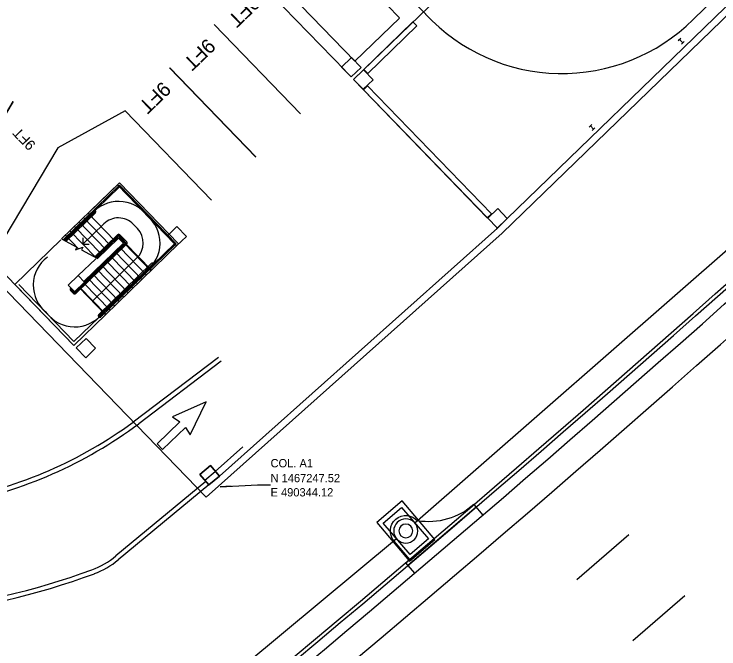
# Model space of a CAD drawing. Extents: x 468143 to 491361, y 1438528 to 1468730.
# Drawn here: x 490314.2 to 490416.5, y 1467224 to 1467316.1 of the extents above; entities that cross this region are included whole.
import ezdxf

# ---------------------------------------------------------------- set-up
doc = ezdxf.new("R2010")
doc.units = 0
doc.layers.add('Default', color=7, linetype='Continuous')
doc.layers.add('Xreference_dp', color=7, linetype='Continuous')

# ---------------------------------------------------------------- blocks, each defined once
blk = doc.blocks.new('POINT_DISPLAY')
at = {"layer": 'Default'}
blk.add_line((0, 0), (0, 0), dxfattribs=at)
blk = doc.blocks.new('InltCurb1_35')
at = {"layer": 'Default'}
for p, q in [((2.25, 2), (2.25, 5.5)), ((-10, 2), (-10, 0)), ((-10, 1.5), (3, 1.5)), ((3, 2), (2.25, 2)), ((3, 0), (3, 2))]:
    blk.add_line(p, q, dxfattribs=at)
for radius in [1.75, 1]:
    blk.add_circle((0, 5.5), radius, dxfattribs=at)
for centre, radius, start, end in [((0, 5.5), 2.25, 0, 180), ((-9.85, 12), 10, 269.1432, 319.4677)]:
    blk.add_arc(centre, radius, start, end, dxfattribs=at)
for p in [(0, 7.75), (0, 7.25), (0, 7.25), (-1.6, 6.2), (-1.22, 6.76), (-0.66, 7.12), (0.7, 7.1), (1.26, 6.72), (1.62, 6.16), (-1.75, 5.5), (-1.75, 5.5), (0, 5.5), (0, 5.5), (1.75, 5.5), (1.75, 5.5), (-1.62, 4.84), (-1.26, 4.28), (1.22, 4.24), (1.6, 4.8), (-0.7, 3.9), (0, 3.75), (0, 3.75), (0.66, 3.88), (0, 0), (0, 0)]:
    blk.add_blockref('POINT_DISPLAY', p, dxfattribs=at)
blk = doc.blocks.new('JBottom35x60')
at = {"layer": 'Default'}
for p, q in [((2.42, 3.67), (-2.42, 3.67)), ((-2.42, 3.67), (-2.42, -3.67)), ((2.42, -3.67), (2.42, 3.67)), ((-1.75, -3), (-1.75, 3)), ((-1.75, 3), (1.75, 3)), ((1.75, 3), (1.75, -3)), ((1.75, -3), (-1.75, -3)), ((-2.42, -3.67), (2.42, -3.67))]:
    blk.add_line(p, q, dxfattribs=at)
for p in [(-1.75, 3), (0, 3), (0, 3), (0, 3), (1.75, 3), (-1.75, 0), (-1.75, 0), (0, 0), (0, 0), (0, 0), (1.75, 0), (1.75, 0), (-1.75, -3), (0, -3), (0, -3), (0, -3), (1.75, -3)]:
    blk.add_blockref('POINT_DISPLAY', p, dxfattribs=at)
blk = doc.blocks.new('STALL 9FT')
at = {"layer": 'Default'}
for points in [[(0, 0), (0, 216)], [(108, 216), (108, 0)]]:
    blk.add_lwpolyline(points, dxfattribs=at)
blk.add_text('9FT', height=25, dxfattribs=at).set_placement((24.7, 7.1))
blk = doc.blocks.new('arrow-thru')
at = {"layer": 'Default'}
blk.add_lwpolyline([(14.99997, 0), (28.999942, 0), (28.999942, 54.99989), (43.999912, 51.999896), (21.999956, 111.999776), (0, 51.999896), (14.99997, 54.99989)], close=True, dxfattribs=at)
blk = doc.blocks.new('Col 16x24')
at = {"layer": 'Default'}
blk.add_lwpolyline([(11.999976, -7.999984), (-11.999976, -7.999984), (-11.999976, 7.999984), (11.999976, 7.999984), (11.999976, -7.999984)], dxfattribs=at)
blk.add_lwpolyline([(-11.999976, -7.999984), (11.999976, -7.999984), (11.999976, 7.999984), (-11.999976, 7.999984)], close=True, dxfattribs=at)
blk = doc.blocks.new('staire lvl 1')
at = {"layer": 'Default'}
for p, q in [((158.5, 259.5), (10.5, 259.5)), ((10.5, 182.5), (10.5, 259.5)), ((158.5, 147.9), (158.5, 259.5)), ((15.5, 254.5), (153.5, 254.5)), ((15.5, 193.5), (15.5, 254.5)), ((76, 197), (83, 197)), ((13.5, 191.5), (13.5, 8.5)), ((15.5, 191.5), (15.5, 10.5)), ((17, 191.5), (17, 63.5)), ((19, 191.5), (19, 63.5)), ((73, 194), (73, 71)), ((75, 194), (75, 71)), ((76, 195), (83, 195)), ((10.5, 182.5), (76.5, 182.5)), ((10.5, 182.5), (10.5, 5.5)), ((10.5, 181.5), (76.5, 181.5)), ((43.5, 182.5), (43.5, 74.5)), ((10.5, 171.5), (76.5, 171.5)), ((10.5, 160.5), (76.5, 160.5)), ((76.5, 71.5), (76.5, 169.5)), ((76.5, 169.5), (76.5, 71.5)), ((78.5, 169.5), (78.5, 73.5)), ((92.5, 169.5), (92.5, 127.1)), ((92.5, 127.1), (92.5, 169.5)), ((10.5, 149.5), (76.5, 149.5)), ((10.5, 138.5), (76.5, 138.5)), ((158.5, 136.5), (125.7, 136.5)), ((150, 143.6), (150, 72.2)), ((152, 144.1), (152, 72.2)), ((153.5, 144.5), (153.5, 10.5)), ((153.5, 144.5), (153.5, 72.2)), ((155.5, 145.1), (155.5, 8.5)), ((155.5, 145.1), (155.5, 72.2)), ((158.5, 5.5), (158.5, 145.9)), ((10.5, 127.5), (76.5, 127.5)), ((90.5, 124.6), (90.5, 73.5)), ((92.5, 71.5), (92.5, 125.1)), ((92.5, 125.1), (92.5, 71.5)), ((158.5, 125.5), (93.9, 125.5)), ((94, 125.5), (94, 71)), ((96, 126.1), (96, 71)), ((126.2, 125.5), (126.2, 74.5)), ((10.5, 116.5), (76.5, 116.5)), ((158.5, 114.5), (92.5, 114.5)), ((10.5, 105.5), (76.5, 105.5)), ((158.5, 103.5), (92.5, 103.5)), ((10.5, 94.5), (76.5, 94.5)), ((158.5, 92.5), (92.5, 92.5)), ((10.5, 83.5), (76.5, 83.5)), ((15.5, 83.5), (15.5, 10.5)), ((158.5, 81.5), (92.5, 81.5)), ((158.5, 10.5), (158.5, 81.5)), ((76.5, 72.5), (10.5, 72.5)), ((10.5, 71.5), (76.5, 71.5)), ((15.5, 62), (16, 62)), ((76, 70), (93, 70)), ((76, 68), (93, 68)), ((76.5, 71.5), (92.5, 71.5)), ((76.5, 71.5), (92.5, 71.5)), ((78.5, 73.5), (90.5, 73.5)), ((152.7, 71.5), (153.5, 71.5)), ((152.7, 69.5), (153.5, 69.5)), ((15.5, 60), (16, 60)), ((90.2, 38.5), (79.5, 38.5)), ((10.5, 10.5), (158.5, 10.5)), ((158.5, 5.5), (10.5, 5.5)), ((155.5, 8.5), (13.5, 8.5)), ((153.5, 10.5), (15.5, 10.5))]:
    blk.add_line(p, q, dxfattribs=at)
for points in [[(158.5, 145.9), (129.6, 136.7), (128.3, 141.7), (122.2, 129.3), (120.9, 134.3), (90.5, 124.6)], [(133.9, 117.9), (126.2, 125.5), (118.6, 117.9)]]:
    blk.add_lwpolyline(points, dxfattribs=at)
for centre, radius, start, end in [((76.5, 193.5), 61, 82.5761, 187.4239), ((92.5, 193.5), 61, 352.5776, 97.4223), ((76, 194), 3, 90, 180), ((83, 194), 3, 360, 90), ((16.2, 191.5), 2.75, 360, 180), ((14.5, 186.5), 1, 360, 180), ((16.2, 191.5), 0.75, 360, 180), ((76, 194), 1, 90, 180), ((83, 194), 1, 360, 90), ((76.5, 71.5), 61, 172.5777, 277.4223), ((79.5, 74.5), 36, 180, 270), ((92.5, 71.5), 61, 262.5777, 7.4223), ((90.2, 74.5), 36, 270, 0), ((15.5, 63.4), 1.53, 290.3084, 2.3112), ((15.5, 63.4), 3.46, 277.6626, 1.1347), ((76, 71), 3, 180, 270), ((76, 71), 1, 180, 270), ((93, 71), 1, 270, 360), ((93, 71), 3, 270, 360), ((152.7, 72.2), 2.75, 180, 270), ((152.7, 72.2), 2.75, 180, 270), ((152.7, 72.2), 0.75, 180, 270)]:
    blk.add_arc(centre, radius, start, end, dxfattribs=at)
at = {"layer": 'Default', "yscale": -1, "rotation": 89.99999999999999}
blk.add_blockref('Col 16x24', (84.5, 181.5), dxfattribs=at)
blk = doc.blocks.new('cable suppt')
at = {"layer": 'Default'}
for points in [[(-3.2, 4), (3.2, 4)], [(0, -4), (0, 4)], [(-3.2, -4), (3.2, -4)]]:
    blk.add_lwpolyline(points, dxfattribs=at)
blk = doc.blocks.new('cable suppt bay')
at = {"layer": 'Default'}
for p in [(227.999544, 0.999998), (443.999112, 0.999998)]:
    blk.add_blockref('cable suppt', p, dxfattribs=at)
blk = doc.blocks.new('STALL 9FT-75D')
at = {"layer": 'Default'}
for p, q in [((0, 0), (111.8, 0)), ((111.8, 0), (167.7, -208.6))]:
    blk.add_line(p, q, dxfattribs=at)
blk.add_lwpolyline([(55.9, -208.6), (0, 0)], dxfattribs=at)
blk.add_text('9FT', height=18, dxfattribs=at).set_placement((86.4, -185.9))
blk = doc.blocks.new('Col 24x24')
at = {"layer": 'Default'}
blk.add_lwpolyline([(-11.999976, -11.999976), (-11.999976, 11.999976), (11.999976, 11.999976), (11.999976, -11.999976), (-11.999976, -11.999976)], dxfattribs=at)
blk.add_lwpolyline([(-11.999976, -11.999976), (11.999976, -11.999976), (11.999976, 11.999976), (-11.999976, 11.999976)], close=True, dxfattribs=at)
blk = doc.blocks.new('stair')
at = {"layer": 'Default', "yscale": -1, "rotation": -90.00000000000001}
blk.add_blockref('Col 16x24', (74, 78), dxfattribs=at)

msp = doc.modelspace()

# ---------------------------------------------------------------- linework, layer by layer
at = {"layer": 'Xreference_dp'}
for p, q in [((490322.87, 1467268.03), (490139.28, 1467457.72)), ((490322.87, 1467268.03), (490139.28, 1467457.72)), ((490459.82, 1467358.12), (490384.21, 1467284.96)), ((490459.82, 1467358.12), (490384.21, 1467284.96)), ((490363.46, 1467306.61), (490403.7, 1467345.55)), ((490363.46, 1467306.61), (490403.7, 1467345.55)), ((490373.92, 1467316.08), (490363.14, 1467327.21)), ((490373.92, 1467316.08), (490363.14, 1467327.21)), ((490423.9, 1467326.12), (490412.71, 1467315.29)), ((490423.9, 1467326.12), (490412.71, 1467315.29)), ((490370.12, 1467315.51), (490363.65, 1467309.25)), ((490370.12, 1467315.51), (490363.65, 1467309.25)), ((490384.32, 1467285.05), (490363.46, 1467306.61)), ((490384.32, 1467285.05), (490363.46, 1467306.61)), ((490330.31, 1467302.04), (490320.57, 1467296.69)), ((490330.31, 1467302.04), (490320.57, 1467296.69)), ((490424.48, 1467287.83), (490372.37, 1467242.27)), ((490384.32, 1467285.05), (490343.99, 1467249.08)), ((490384.32, 1467285.05), (490343.99, 1467249.08)), ((490343.85, 1467266.28), (490331.51, 1467256.93)), ((490343.85, 1467266.28), (490331.51, 1467256.93)), ((490344.25, 1467265.75), (490332.29, 1467256.68)), ((490344.25, 1467265.75), (490332.29, 1467256.68)), ((490342.02, 1467248.32), (490328.98, 1467237.52)), ((490342.02, 1467248.32), (490328.98, 1467237.52)), ((490342.45, 1467247.8), (490329.33, 1467236.95)), ((490342.45, 1467247.8), (490329.33, 1467236.95)), ((490403.4, 1467240.58), (490395.83, 1467234.05)), ((490369.71, 1467239.99), (490323.94, 1467201.99)), ((490411.52, 1467231.74), (490403.95, 1467225.2))]:
    msp.add_line(p, q, dxfattribs=at)
msp.add_lwpolyline([(490342.06, 1467246.02), (490137.16, 1467457.76), (490471.58, 1467781.33), (490516.38, 1467735.04), (490628.6, 1467843.61), (490790.28, 1467676.55), (490385, 1467284.32)], close=True, dxfattribs=at)
msp.add_lwpolyline([(490342.06, 1467246.02), (490137.16, 1467457.76), (490471.58, 1467781.33), (490516.38, 1467735.04), (490628.6, 1467843.61), (490790.28, 1467676.55), (490385, 1467284.32)], close=True, dxfattribs=at)
for points in [[(490364.94, 1467308.04), (490372.08, 1467314.96), (490372.66, 1467314.36), (490365.52, 1467307.45), (490364.94, 1467308.04)], [(490364.94, 1467308.04), (490372.08, 1467314.96), (490372.66, 1467314.36), (490365.52, 1467307.45), (490364.94, 1467308.04)], [(490382.86, 1467286.53), (490364.9, 1467305.09), (490365.5, 1467305.67), (490383.46, 1467287.11), (490382.86, 1467286.53)], [(490382.86, 1467286.53), (490364.9, 1467305.09), (490365.5, 1467305.67), (490383.46, 1467287.11), (490382.86, 1467286.53)], [(490341.87, 1467248.51), (490343.39, 1467249.77), (490347.4, 1467253.34)], [(490341.87, 1467248.51), (490343.39, 1467249.77), (490347.4, 1467253.34)], [(490345.7, 1467247.62), (490344.11, 1467247.52), (490349.51, 1467247.84), (490351.42, 1467247.84)], [(490345.7, 1467247.62), (490344.11, 1467247.52), (490349.51, 1467247.84), (490351.42, 1467247.84)]]:
    msp.add_lwpolyline(points, dxfattribs=at)
for centre, radius, start, end in [((488571.3, 1469355.06), 2903.53, 306.9274, 317.95297), ((488571.3, 1469355.06), 2904.28, 306.9274, 317.95297), ((488571.3, 1469355.06), 2905.78, 306.9274, 317.95297), ((488571.3, 1469355.06), 2911.78, 306.9274, 317.95297), ((488571.3, 1469355.06), 2923.78, 306.9274, 317.95297), ((488571.3, 1469355.06), 2935.78, 306.9274, 317.95297), ((488571.3, 1469355.06), 2947.78, 306.9274, 317.95297), ((488571.3, 1469355.06), 2947.78, 306.9274, 317.95297), ((488571.3, 1469355.06), 2949.28, 306.9274, 317.95297), ((488571.3, 1469355.06), 2949.78, 306.9274, 317.95297), ((490393.69, 1467334.45), 27, 222.9011, 314.7804), ((490393.69, 1467334.45), 27, 222.9011, 314.7804), ((488571.3, 1469355.06), 2779.78, 306.9274, 312.53817), ((488571.3, 1469355.06), 2780.28, 306.9274, 312.53817), ((488571.3, 1469355.06), 2781.78, 306.9274, 312.53817), ((488571.3, 1469355.06), 2785.78, 306.41751, 312.53817), ((490294.19, 1467307.69), 63, 280.6693, 306.3185), ((490294.19, 1467307.69), 63, 280.6693, 306.3185), ((490294.19, 1467307.69), 63.66, 280.6693, 306.7585), ((490294.19, 1467307.69), 63.66, 280.6693, 306.7585), ((490321.33, 1467246.76), 12, 290.2922, 309.6166), ((490321.33, 1467246.76), 12, 290.2922, 309.6166), ((490321.68, 1467246.19), 12, 290.3827, 309.6166), ((490321.68, 1467246.19), 12, 290.3827, 309.6166), ((490289.34, 1467333.26), 104.22, 261.1671, 290.2922), ((490289.34, 1467333.26), 104.22, 261.1671, 290.2922), ((490289.32, 1467333.28), 104.91, 261.2228, 290.3827), ((490289.32, 1467333.28), 104.91, 261.2228, 290.3827)]:
    msp.add_arc(centre, radius, start, end, dxfattribs=at)

# ---------------------------------------------------------------- block references
for name, p, xscale, yscale, rotation in [('STALL 9FT', (490357.61, 1467328.45), 0.08333072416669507, 0.08333072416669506, -135.94293275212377), ('STALL 9FT', (490357.61, 1467328.45), 0.08333072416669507, 0.08333072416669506, -135.94293275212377), ('STALL 9FT', (490349.72, 1467320.81), 0.08333072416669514, 0.08333072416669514, -135.9429327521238), ('STALL 9FT', (490349.72, 1467320.81), 0.08333072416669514, 0.08333072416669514, -135.9429327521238), ('STALL 9FT', (490343.25, 1467314.55), 0.08333072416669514, 0.08333072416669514, -135.9429327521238), ('STALL 9FT', (490343.25, 1467314.55), 0.08333072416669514, 0.08333072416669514, -135.9429327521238), ('cable suppt bay', (490424.58, 1467325.41), 0.08333072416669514, 0.08333072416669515, -135.9370632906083), ('cable suppt bay', (490424.58, 1467325.41), 0.08333072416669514, 0.08333072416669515, -135.9370632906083), ('STALL 9FT-75D', (490304.84, 1467287.95), 0.0833307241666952, 0.08333072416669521, 134.05706724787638), ('STALL 9FT-75D', (490304.84, 1467287.95), 0.0833307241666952, 0.08333072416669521, 134.05706724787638), ('Col 24x24', (490363.13, 1467308.38), 0.0833307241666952, 0.0833307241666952, 44.062944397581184), ('Col 24x24', (490363.13, 1467308.38), 0.0833307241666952, 0.0833307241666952, 44.062944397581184), ('STALL 9FT', (490336.78, 1467308.29), 0.08333072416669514, 0.08333072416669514, -135.9429327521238), ('STALL 9FT', (490336.78, 1467308.29), 0.08333072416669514, 0.08333072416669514, -135.9429327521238), ('Col 24x24', (490364.87, 1467306.59), 0.0833307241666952, 0.0833307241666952, 44.062944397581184), ('Col 24x24', (490364.87, 1467306.59), 0.0833307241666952, 0.0833307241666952, 44.062944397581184), ('STALL 9FT-75D', (490311.32, 1467281.26), 0.0833307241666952, 0.08333072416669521, 134.05706724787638), ('STALL 9FT-75D', (490311.32, 1467281.26), 0.0833307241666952, 0.08333072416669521, 134.05706724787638), ('staire lvl 1', (490339.02, 1467282.44), 0.08333072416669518, 0.0833307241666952, 134.06293670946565), ('staire lvl 1', (490339.02, 1467282.44), 0.08333072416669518, 0.0833307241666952, 134.06293670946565), ('Col 24x24', (490384.35, 1467286.47), 0.0833307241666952, 0.0833307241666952, 44.062944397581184), ('Col 24x24', (490384.35, 1467286.47), 0.0833307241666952, 0.0833307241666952, 44.062944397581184), ('Col 24x24', (490337.81, 1467283.87), 0.0833307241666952, 0.0833307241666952, 44.062944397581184), ('Col 24x24', (490337.81, 1467283.87), 0.0833307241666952, 0.0833307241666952, 44.062944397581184), ('stair', (490322.87, 1467268.03), 0.0833307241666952, -0.0833307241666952, 134.0629443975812), ('stair', (490322.87, 1467268.03), 0.0833307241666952, -0.0833307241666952, 134.0629443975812), ('Col 24x24', (490324.63, 1467267.64), 0.0833307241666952, 0.0833307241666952, 44.062944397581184), ('Col 24x24', (490324.63, 1467267.64), 0.0833307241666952, 0.0833307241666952, 44.062944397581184), ('arrow-thru', (490334.08, 1467254.68), 0.08333072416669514, 0.08333072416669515, -45.942932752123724), ('arrow-thru', (490334.08, 1467254.68), 0.08333072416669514, 0.08333072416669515, -45.942932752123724), ('Col 24x24', (490342.58, 1467249.21), 0.0833307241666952, 0.08333072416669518, 39.61659952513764), ('Col 24x24', (490342.58, 1467249.21), 0.0833307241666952, 0.08333072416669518, 39.61659952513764)]:
    msp.add_blockref(name, p, dxfattribs=dict(at, xscale=xscale, yscale=yscale, rotation=rotation))
at = {"layer": 'Xreference_dp', "yscale": -1.0000000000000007, "rotation": -139.49096969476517}
msp.add_blockref('InltCurb1_35', (490374.61, 1467236.95), dxfattribs=at)
at = {"layer": 'Xreference_dp', "rotation": 40.50903030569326}
msp.add_blockref('JBottom35x60', (490371.04, 1467241.13), dxfattribs=at)

# ---------------------------------------------------------------- texts
at = {"layer": 'Xreference_dp'}
for s, p in [('COL. A1', (490351.42, 1467250.36)), ('COL. A1', (490351.42, 1467250.36)), ('N 1467247.52', (490351.42, 1467248.2)), ('N 1467247.52', (490351.42, 1467248.2)), ('E 490344.12', (490351.42, 1467246.14)), ('E 490344.12', (490351.42, 1467246.14))]:
    msp.add_text(s, height=1.2, dxfattribs=at).set_placement(p)

doc.saveas('drawing.dxf')
